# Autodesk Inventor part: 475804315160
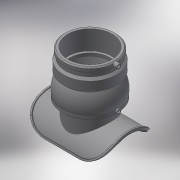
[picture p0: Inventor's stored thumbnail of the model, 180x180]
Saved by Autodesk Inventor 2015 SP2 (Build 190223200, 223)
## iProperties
Created: 2017-08
Part Number: 475804315160
Material: Generic
Description: PLASSON WASTEWATER SADDLE 280-315x160 EF ADJUSTABLE INLET
Document SubType Name: Modeling
Designer: Кирилл
Density: 1 g/cm^3
Appearance: Default
Author: Кирилл
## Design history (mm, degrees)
derived "475804.ipt"
feature "Solid1::475804.ipt"
feature "Solid2::475804.ipt"
tag "TaggingFeature1"
body "Solid1"
body "Solid2"
other parameters: "d0" = 161.6, "d3" = 45 deg, "d4" = 184, "d5" = 176, "d6" = 142.208, "d7" = 129.28, "d8" = 144, "d13" = 45 deg, "d15" = 135 deg, "d17" = 192, "d18" = 45 deg, "d19" = 80.8, "d22" = 4, "d23" = 16.16, "d25" = 45 deg, "d26" = 15 deg, "d27" = 262.6, "d28" = 136, "d29" = 156.8, "d31" = 315, "d32" = 202, "d37" = 0, "d38" = 247, "d39" = 123.5, "d40" = 330.75, "d42" = 0, "d52" = 98.8, "d53" = 6.175, "d55" = 0.988, "d56" = 224, "d57" = 0, "d58" = 105, "d59" = 15, "d61" = 5 deg, "d62" = 15, "d65" = 4, "d66" = 4, "d67" = 14, "d68" = 0, "d69" = 3, "d70" = 0, "d_" = 315, "B_" = 247, "H_" = 202, "A_" = 105, "d21" = 4
